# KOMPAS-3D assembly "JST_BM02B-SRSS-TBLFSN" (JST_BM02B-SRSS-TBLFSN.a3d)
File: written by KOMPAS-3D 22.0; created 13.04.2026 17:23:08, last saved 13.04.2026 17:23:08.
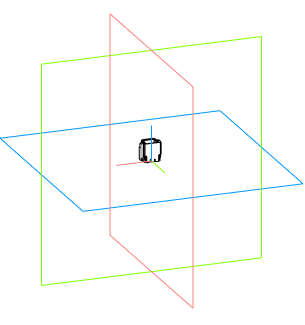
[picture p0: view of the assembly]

Document properties: Автор: Andrey; Полное имя файла: C:\Users\User1\Documents\JST_BM02B-SRSS-TBLFSN.a3d

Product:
- Component [assembly]: BM02B-SRSS-TB (LF)(SN)  | qty 1  | source file: BM02B-SRSS-TB (LF)(SN).a3d
- Part/product: JST_BM02B-SRSS-TBLFSN
    Комментарий: JST_BM02B-SRSS-TBLFSN

Referenced files in C:\Users\User1\Documents\: BM02B-SRSS-TB (LF)(SN).a3d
